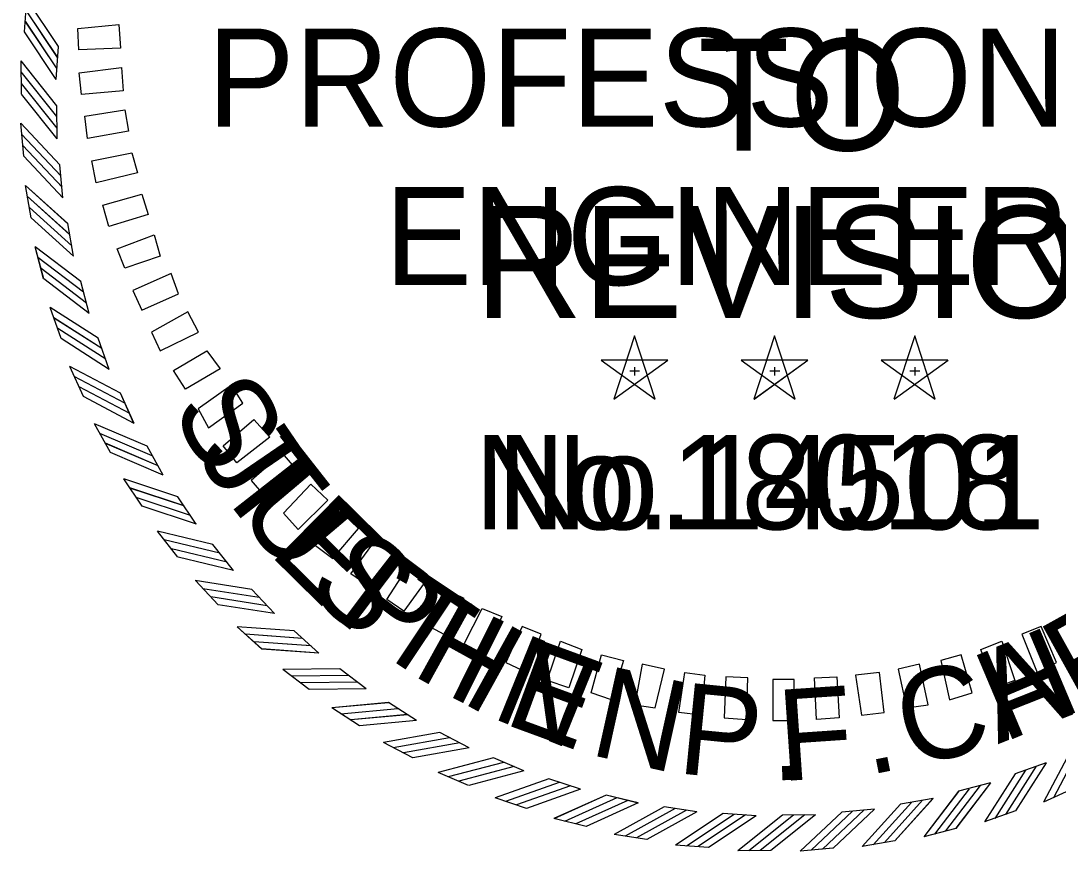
# Model space of a CAD drawing. Extents: x 16 to 1228740, y 11 to 152440.
# Drawn here: x 17.6793 to 17.7977, y 10.8149 to 10.9098 of the extents above; entities that cross this region are included whole.
import ezdxf

# ---------------------------------------------------------------- set-up
doc = ezdxf.new("R2010")
doc.units = 0
for name, color, linetype in [('STAMP_FRED', 7, 'Continuous'), ('STAMP_JUSTIN', 7, 'Continuous'), ('STAMP_PRELIM', 7, 'Continuous')]:
    doc.layers.add(name, color=color, linetype=linetype)

msp = doc.modelspace()

# ---------------------------------------------------------------- linework, layer by layer
at = {"layer": 'STAMP_FRED'}
for p, q in [((17.6797, 10.90852), (17.67998, 10.91228)), ((17.68332, 10.9031), (17.6836, 10.90687)), ((17.67937, 10.90143), (17.67934, 10.9052)), ((17.68343, 10.89632), (17.68339, 10.9001)), ((17.67963, 10.89432), (17.67928, 10.89808)), ((17.68409, 10.88957), (17.68375, 10.89333)), ((17.68047, 10.88727), (17.67982, 10.89098)), ((17.68531, 10.8829), (17.68466, 10.88662)), ((17.68189, 10.8803), (17.68093, 10.88395)), ((17.68708, 10.87635), (17.68612, 10.88)), ((17.68389, 10.87348), (17.68263, 10.87704)), ((17.68938, 10.86997), (17.68812, 10.87353)), ((17.74935, 10.87379), (17.747, 10.86655)), ((17.7517, 10.86656), (17.74936, 10.8738)), ((17.76534, 10.87379), (17.76299, 10.86655)), ((17.76769, 10.86656), (17.76535, 10.8738)), ((17.78134, 10.87379), (17.77898, 10.86655)), ((17.78369, 10.86656), (17.78134, 10.8738)), ((17.75316, 10.87103), (17.74555, 10.87103)), ((17.74555, 10.87103), (17.7517, 10.86655)), ((17.747, 10.86656), (17.75317, 10.87102)), ((17.76915, 10.87103), (17.76154, 10.87103)), ((17.76154, 10.87103), (17.7677, 10.86655)), ((17.763, 10.86656), (17.76916, 10.87102)), ((17.78514, 10.87103), (17.77753, 10.87103)), ((17.77753, 10.87103), (17.78369, 10.86655)), ((17.77899, 10.86656), (17.78515, 10.87102)), ((17.68644, 10.86685), (17.68489, 10.87029)), ((17.74881, 10.86981), (17.74994, 10.86981)), ((17.74936, 10.87022), (17.74936, 10.86926)), ((17.7648, 10.86981), (17.76593, 10.86981)), ((17.76535, 10.87022), (17.76535, 10.86926)), ((17.78079, 10.86981), (17.78193, 10.86981)), ((17.78134, 10.87022), (17.78134, 10.86926)), ((17.6922, 10.8638), (17.69065, 10.86725)), ((17.68952, 10.86045), (17.6877, 10.86375)), ((17.69552, 10.85789), (17.6937, 10.8612)), ((17.69313, 10.85433), (17.69104, 10.85746)), ((17.69932, 10.85227), (17.69723, 10.85541)), ((17.69723, 10.84852), (17.69489, 10.85148)), ((17.70357, 10.84698), (17.70122, 10.84994)), ((17.7018, 10.84308), (17.69922, 10.84583)), ((17.70824, 10.84207), (17.70566, 10.84482)), ((17.7068, 10.83802), (17.704, 10.84055)), ((17.7133, 10.83755), (17.7105, 10.84009)), ((17.71219, 10.8334), (17.7092, 10.83569)), ((17.71872, 10.83347), (17.71571, 10.83576)), ((17.72445, 10.82985), (17.72127, 10.83189)), ((17.71796, 10.82925), (17.71478, 10.83128)), ((17.73047, 10.82672), (17.72713, 10.82848)), ((17.72404, 10.82558), (17.72071, 10.82734)), ((17.73672, 10.82409), (17.73325, 10.82557)), ((17.79637, 10.82502), (17.79281, 10.82376)), ((17.73041, 10.82242), (17.72695, 10.82391)), ((17.74317, 10.82199), (17.73958, 10.82318)), ((17.78999, 10.82272), (17.78633, 10.82176)), ((17.79949, 10.82207), (17.79605, 10.82052)), ((17.73702, 10.81981), (17.73344, 10.821)), ((17.74977, 10.82042), (17.7461, 10.82132)), ((17.78344, 10.82095), (17.77972, 10.82029)), ((17.75647, 10.81941), (17.75274, 10.82)), ((17.77677, 10.81973), (17.77301, 10.81938)), ((17.74382, 10.81774), (17.74016, 10.81864)), ((17.76324, 10.81896), (17.75947, 10.81924)), ((17.77002, 10.81906), (17.76624, 10.81903)), ((17.79286, 10.81952), (17.7893, 10.81826)), ((17.78603, 10.81753), (17.78239, 10.81657)), ((17.75077, 10.81625), (17.74704, 10.81684)), ((17.77907, 10.81611), (17.77536, 10.81545)), ((17.75781, 10.81533), (17.75405, 10.81561)), ((17.76491, 10.815), (17.76114, 10.81497)), ((17.77202, 10.81526), (17.76826, 10.81492))]:
    msp.add_line(p, q, dxfattribs=at)
for points in [[(17.6836, 10.90686), (17.67997, 10.91229)], [(17.68349, 10.90561), (17.67987, 10.91104)], [(17.68343, 10.9043), (17.6798, 10.90973)], [(17.68333, 10.90309), (17.6797, 10.90852)], [(17.68339, 10.90009), (17.67933, 10.9052)], [(17.68339, 10.89884), (17.67933, 10.90394)], [(17.68343, 10.89753), (17.67937, 10.90263)], [(17.68343, 10.89631), (17.67937, 10.90142)], [(17.68375, 10.89333), (17.67928, 10.89808)], [(17.68385, 10.89208), (17.67938, 10.89683)], [(17.684, 10.89077), (17.67953, 10.89553)], [(17.6841, 10.88956), (17.67963, 10.89432)], [(17.68466, 10.88661), (17.67981, 10.89098)], [(17.68486, 10.88538), (17.68002, 10.88974)], [(17.68512, 10.88409), (17.68028, 10.88846)], [(17.68532, 10.88289), (17.68047, 10.88726)], [(17.68612, 10.88), (17.68093, 10.88395)], [(17.68643, 10.87878), (17.68124, 10.88274)], [(17.68679, 10.87752), (17.6816, 10.88148)], [(17.68709, 10.87635), (17.6819, 10.8803)], [(17.68812, 10.87353), (17.68263, 10.87704)], [(17.68853, 10.87234), (17.68303, 10.87585)], [(17.68899, 10.87112), (17.6835, 10.87463)], [(17.68939, 10.86997), (17.68389, 10.87348)], [(17.69065, 10.86724), (17.68489, 10.87029)], [(17.69116, 10.86609), (17.68539, 10.86914)], [(17.69172, 10.86491), (17.68595, 10.86796)], [(17.69221, 10.8638), (17.68644, 10.86685)], [(17.6937, 10.86119), (17.6877, 10.86375)], [(17.69429, 10.86009), (17.68829, 10.86265)], [(17.69495, 10.85895), (17.68895, 10.86151)], [(17.69553, 10.85789), (17.68953, 10.86045)], [(17.69723, 10.85541), (17.69104, 10.85746)], [(17.69791, 10.85436), (17.69172, 10.85641)], [(17.69866, 10.85328), (17.69247, 10.85534)], [(17.69933, 10.85227), (17.69314, 10.85432)], [(17.70122, 10.84994), (17.69488, 10.85148)], [(17.70199, 10.84895), (17.69566, 10.85049)], [(17.70283, 10.84794), (17.69649, 10.84948)], [(17.70358, 10.84698), (17.69724, 10.84852)], [(17.70566, 10.84482), (17.69921, 10.84583)], [(17.70651, 10.84389), (17.70006, 10.8449)], [(17.70743, 10.84296), (17.70098, 10.84397)], [(17.70825, 10.84207), (17.7018, 10.84307)], [(17.7105, 10.84008), (17.70399, 10.84055)], [(17.71142, 10.83923), (17.70492, 10.8397)], [(17.71241, 10.83837), (17.70591, 10.83885)], [(17.71331, 10.83755), (17.7068, 10.83802)], [(17.71572, 10.83576), (17.70919, 10.83569)], [(17.71671, 10.83499), (17.71019, 10.83492)], [(17.71777, 10.83422), (17.71124, 10.83415)], [(17.71872, 10.83347), (17.7122, 10.8334)], [(17.72127, 10.83188), (17.71478, 10.83128)], [(17.72232, 10.8312), (17.71583, 10.83059)], [(17.72344, 10.83051), (17.71695, 10.82991)], [(17.72446, 10.82985), (17.71796, 10.82925)], [(17.72713, 10.82848), (17.72071, 10.82734)], [(17.72823, 10.82788), (17.72181, 10.82674)], [(17.72941, 10.82729), (17.72298, 10.82615)], [(17.80024, 10.82679), (17.7972, 10.82102)], [(17.73047, 10.82672), (17.72405, 10.82558)], [(17.73325, 10.82557), (17.72694, 10.8239)], [(17.79909, 10.82629), (17.79605, 10.82052)], [(17.7344, 10.82507), (17.72809, 10.8234)], [(17.73561, 10.82458), (17.72931, 10.82291)], [(17.79522, 10.82463), (17.79171, 10.81913)], [(17.79637, 10.82502), (17.79286, 10.81953)], [(17.73673, 10.82409), (17.73042, 10.82242)], [(17.79281, 10.82376), (17.7893, 10.81826)], [(17.794, 10.82417), (17.79049, 10.81867)], [(17.73959, 10.82318), (17.73344, 10.821)], [(17.74077, 10.82277), (17.73463, 10.82059)], [(17.74203, 10.82238), (17.73588, 10.8202)], [(17.78756, 10.82206), (17.7836, 10.81687)], [(17.78882, 10.82242), (17.78486, 10.81723)], [(17.78999, 10.82272), (17.78604, 10.81753)], [(17.74317, 10.82199), (17.73703, 10.81981)], [(17.7461, 10.82131), (17.74015, 10.81863)], [(17.74732, 10.82101), (17.74137, 10.81833)], [(17.78345, 10.82095), (17.77908, 10.81611)], [(17.78634, 10.82175), (17.78239, 10.81657)], [(17.7486, 10.82072), (17.74265, 10.81804)], [(17.74977, 10.82043), (17.74383, 10.81775)], [(17.75274, 10.82), (17.74704, 10.81683)], [(17.75398, 10.81979), (17.74828, 10.81663)], [(17.77677, 10.81973), (17.77202, 10.81527)], [(17.77972, 10.82029), (17.77536, 10.81545)], [(17.78096, 10.8205), (17.77659, 10.81565)], [(17.78225, 10.82075), (17.77788, 10.81591)], [(17.75528, 10.81961), (17.74958, 10.81645)], [(17.75648, 10.81942), (17.75077, 10.81625)], [(17.75948, 10.81923), (17.75405, 10.81561)], [(17.76073, 10.81913), (17.7553, 10.81551)], [(17.76204, 10.81906), (17.75661, 10.81544)], [(17.76324, 10.81896), (17.75782, 10.81534)], [(17.76625, 10.81903), (17.76114, 10.81497)], [(17.7675, 10.81903), (17.7624, 10.81497)], [(17.76881, 10.81907), (17.76371, 10.81501)], [(17.77003, 10.81907), (17.76492, 10.81501)], [(17.77301, 10.81938), (17.76826, 10.81491)], [(17.77426, 10.81948), (17.76951, 10.81502)], [(17.77556, 10.81963), (17.77081, 10.81517)]]:
    msp.add_lwpolyline(points, dxfattribs=at)
at = {"layer": 'STAMP_JUSTIN'}
for p, q in [((17.6797, 10.90853), (17.67998, 10.91228)), ((17.68332, 10.9031), (17.6836, 10.90687)), ((17.67937, 10.90143), (17.67934, 10.9052)), ((17.68343, 10.89632), (17.6834, 10.9001)), ((17.67963, 10.89432), (17.67928, 10.89808)), ((17.6841, 10.88957), (17.68375, 10.89333)), ((17.68047, 10.88727), (17.67982, 10.89098)), ((17.68532, 10.8829), (17.68466, 10.88662)), ((17.6819, 10.88031), (17.68094, 10.88395)), ((17.68708, 10.87635), (17.68612, 10.88001)), ((17.68389, 10.87348), (17.68263, 10.87704)), ((17.68939, 10.86997), (17.68813, 10.87353)), ((17.74935, 10.87379), (17.747, 10.86655)), ((17.7517, 10.86656), (17.74936, 10.8738)), ((17.76534, 10.87379), (17.76299, 10.86655)), ((17.76769, 10.86656), (17.76535, 10.8738)), ((17.78134, 10.87379), (17.77898, 10.86655)), ((17.78369, 10.86656), (17.78134, 10.8738)), ((17.75316, 10.87103), (17.74555, 10.87103)), ((17.74555, 10.87103), (17.7517, 10.86655)), ((17.747, 10.86656), (17.75317, 10.87103)), ((17.76915, 10.87103), (17.76154, 10.87103)), ((17.76154, 10.87103), (17.7677, 10.86655)), ((17.76299, 10.86656), (17.76916, 10.87103)), ((17.78514, 10.87103), (17.77753, 10.87103)), ((17.77753, 10.87103), (17.78369, 10.86655)), ((17.77899, 10.86656), (17.78515, 10.87103)), ((17.68644, 10.86685), (17.68489, 10.87029)), ((17.74881, 10.86981), (17.74994, 10.86981)), ((17.74936, 10.87022), (17.74936, 10.86926)), ((17.7648, 10.86981), (17.76593, 10.86981)), ((17.76535, 10.87022), (17.76535, 10.86926)), ((17.78079, 10.86981), (17.78193, 10.86981)), ((17.78134, 10.87022), (17.78134, 10.86926)), ((17.69221, 10.8638), (17.69066, 10.86725)), ((17.68953, 10.86045), (17.6877, 10.86375)), ((17.69553, 10.85789), (17.6937, 10.8612)), ((17.69313, 10.85433), (17.69104, 10.85747)), ((17.69932, 10.85227), (17.69723, 10.85542)), ((17.69723, 10.84852), (17.69489, 10.85148)), ((17.70357, 10.84699), (17.70122, 10.84995)), ((17.7018, 10.84308), (17.69922, 10.84583)), ((17.70824, 10.84207), (17.70566, 10.84483)), ((17.7068, 10.83803), (17.704, 10.84055)), ((17.7133, 10.83755), (17.7105, 10.84009)), ((17.7122, 10.83341), (17.7092, 10.83569)), ((17.71872, 10.83347), (17.71572, 10.83577)), ((17.72445, 10.82985), (17.72127, 10.83189)), ((17.71796, 10.82925), (17.71478, 10.83128)), ((17.73047, 10.82672), (17.72713, 10.82849)), ((17.72404, 10.82558), (17.72071, 10.82734)), ((17.73672, 10.82409), (17.73325, 10.82558)), ((17.79637, 10.82502), (17.7928, 10.82376)), ((17.73041, 10.82243), (17.72695, 10.82391)), ((17.74317, 10.82199), (17.73958, 10.82318)), ((17.78999, 10.82272), (17.78633, 10.82176)), ((17.79949, 10.82207), (17.79605, 10.82053)), ((17.73702, 10.81981), (17.73344, 10.821)), ((17.74977, 10.82043), (17.7461, 10.82132)), ((17.78344, 10.82095), (17.77972, 10.8203)), ((17.75647, 10.81942), (17.75274, 10.82)), ((17.77677, 10.81973), (17.77301, 10.81939)), ((17.74382, 10.81775), (17.74016, 10.81864)), ((17.76324, 10.81896), (17.75947, 10.81924)), ((17.77002, 10.81907), (17.76624, 10.81903)), ((17.79285, 10.81952), (17.7893, 10.81827)), ((17.78603, 10.81753), (17.78239, 10.81657)), ((17.75077, 10.81625), (17.74704, 10.81684)), ((17.77907, 10.81611), (17.77536, 10.81545)), ((17.75781, 10.81534), (17.75405, 10.81561)), ((17.76491, 10.81501), (17.76114, 10.81497)), ((17.77201, 10.81527), (17.76826, 10.81492))]:
    msp.add_line(p, q, dxfattribs=at)
for points in [[(17.6836, 10.90686), (17.67998, 10.91229)], [(17.6835, 10.90561), (17.67987, 10.91104)], [(17.68343, 10.9043), (17.67981, 10.90973)], [(17.68333, 10.9031), (17.6797, 10.90852)], [(17.68339, 10.90009), (17.67933, 10.9052)], [(17.68339, 10.89884), (17.67933, 10.90394)], [(17.68343, 10.89753), (17.67938, 10.90263)], [(17.68343, 10.89631), (17.67938, 10.90142)], [(17.68375, 10.89333), (17.67928, 10.89808)], [(17.68385, 10.89208), (17.67938, 10.89683)], [(17.684, 10.89077), (17.67953, 10.89553)], [(17.6841, 10.88957), (17.67963, 10.89432)], [(17.68466, 10.88662), (17.67981, 10.89098)], [(17.68487, 10.88538), (17.68002, 10.88975)], [(17.68512, 10.88409), (17.68028, 10.88846)], [(17.68532, 10.8829), (17.68048, 10.88726)], [(17.68612, 10.88), (17.68093, 10.88395)], [(17.68643, 10.87878), (17.68124, 10.88274)], [(17.68679, 10.87752), (17.6816, 10.88148)], [(17.68709, 10.87635), (17.6819, 10.8803)], [(17.68812, 10.87353), (17.68263, 10.87704)], [(17.68853, 10.87234), (17.68304, 10.87585)], [(17.689, 10.87112), (17.6835, 10.87463)], [(17.68939, 10.86997), (17.68389, 10.87348)], [(17.69066, 10.86725), (17.68489, 10.87029)], [(17.69116, 10.8661), (17.68539, 10.86914)], [(17.69172, 10.86491), (17.68596, 10.86796)], [(17.69221, 10.8638), (17.68644, 10.86685)], [(17.6937, 10.86119), (17.6877, 10.86375)], [(17.69429, 10.86009), (17.68829, 10.86265)], [(17.69495, 10.85896), (17.68895, 10.86152)], [(17.69553, 10.85789), (17.68953, 10.86045)], [(17.69723, 10.85541), (17.69104, 10.85747)], [(17.69792, 10.85436), (17.69172, 10.85642)], [(17.69867, 10.85329), (17.69247, 10.85534)], [(17.69933, 10.85227), (17.69314, 10.85433)], [(17.70122, 10.84994), (17.69489, 10.85148)], [(17.702, 10.84895), (17.69566, 10.85049)], [(17.70283, 10.84794), (17.69649, 10.84948)], [(17.70358, 10.84698), (17.69724, 10.84852)], [(17.70566, 10.84482), (17.69921, 10.84583)], [(17.70651, 10.8439), (17.70006, 10.8449)], [(17.70743, 10.84296), (17.70098, 10.84397)], [(17.70825, 10.84207), (17.7018, 10.84308)], [(17.7105, 10.84008), (17.704, 10.84056)], [(17.71143, 10.83923), (17.70492, 10.8397)], [(17.71242, 10.83838), (17.70591, 10.83885)], [(17.71331, 10.83755), (17.7068, 10.83803)], [(17.71572, 10.83576), (17.7092, 10.83569)], [(17.71671, 10.83499), (17.71019, 10.83492)], [(17.71777, 10.83422), (17.71124, 10.83415)], [(17.71872, 10.83347), (17.7122, 10.83341)], [(17.72127, 10.83189), (17.71478, 10.83128)], [(17.72233, 10.8312), (17.71583, 10.83059)], [(17.72344, 10.83052), (17.71695, 10.82991)], [(17.72446, 10.82985), (17.71796, 10.82925)], [(17.72713, 10.82848), (17.72071, 10.82734)], [(17.72824, 10.82788), (17.72181, 10.82674)], [(17.72941, 10.8273), (17.72298, 10.82616)], [(17.80024, 10.8268), (17.7972, 10.82103)], [(17.73047, 10.82672), (17.72405, 10.82558)], [(17.73325, 10.82557), (17.72694, 10.82391)], [(17.79909, 10.82629), (17.79605, 10.82052)], [(17.7344, 10.82507), (17.72809, 10.8234)], [(17.73561, 10.82458), (17.72931, 10.82291)], [(17.79522, 10.82463), (17.79171, 10.81913)], [(17.79637, 10.82503), (17.79286, 10.81953)], [(17.73673, 10.82409), (17.73042, 10.82243)], [(17.79281, 10.82376), (17.7893, 10.81826)], [(17.794, 10.82417), (17.79049, 10.81867)], [(17.73959, 10.82318), (17.73344, 10.821)], [(17.74077, 10.82277), (17.73463, 10.82059)], [(17.74203, 10.82239), (17.73588, 10.8202)], [(17.78756, 10.82206), (17.7836, 10.81688)], [(17.78882, 10.82243), (17.78486, 10.81724)], [(17.78999, 10.82272), (17.78604, 10.81754)], [(17.74317, 10.82199), (17.73703, 10.81981)], [(17.7461, 10.82132), (17.74015, 10.81864)], [(17.74732, 10.82101), (17.74137, 10.81833)], [(17.78344, 10.82096), (17.77908, 10.81611)], [(17.78634, 10.82176), (17.78238, 10.81657)], [(17.7486, 10.82073), (17.74265, 10.81805)], [(17.74977, 10.82043), (17.74383, 10.81775)], [(17.75274, 10.82), (17.74704, 10.81684)], [(17.75398, 10.81979), (17.74828, 10.81663)], [(17.77677, 10.81974), (17.77202, 10.81527)], [(17.77972, 10.82029), (17.77536, 10.81545)], [(17.78096, 10.8205), (17.77659, 10.81566)], [(17.78225, 10.82076), (17.77788, 10.81591)], [(17.75528, 10.81962), (17.74958, 10.81645)], [(17.75648, 10.81942), (17.75077, 10.81626)], [(17.75948, 10.81924), (17.75405, 10.81561)], [(17.76073, 10.81913), (17.7553, 10.81551)], [(17.76204, 10.81906), (17.75661, 10.81544)], [(17.76324, 10.81896), (17.75782, 10.81534)], [(17.76625, 10.81903), (17.76114, 10.81497)], [(17.7675, 10.81903), (17.7624, 10.81497)], [(17.76881, 10.81907), (17.76371, 10.81501)], [(17.77003, 10.81907), (17.76492, 10.81501)], [(17.77301, 10.81938), (17.76826, 10.81492)], [(17.77426, 10.81949), (17.76951, 10.81502)], [(17.77556, 10.81964), (17.77081, 10.81517)]]:
    msp.add_lwpolyline(points, dxfattribs=at)
at = {"layer": 'STAMP_PRELIM'}
for p, q in [((17.68578, 10.90891), (17.69046, 10.90935)), ((17.6859, 10.90647), (17.68578, 10.90891)), ((17.69046, 10.90935), (17.69065, 10.90666)), ((17.69065, 10.90666), (17.6859, 10.90647)), ((17.68596, 10.90385), (17.69078, 10.90447)), ((17.68621, 10.90135), (17.68596, 10.90385)), ((17.69078, 10.90447), (17.69096, 10.90178)), ((17.69096, 10.90178), (17.68621, 10.90135)), ((17.68659, 10.89891), (17.69115, 10.8996)), ((17.69115, 10.8996), (17.69159, 10.89716)), ((17.6869, 10.89635), (17.68659, 10.89891)), ((17.69159, 10.89716), (17.6869, 10.89635)), ((17.6874, 10.89378), (17.69196, 10.89472)), ((17.69196, 10.89472), (17.69259, 10.89241)), ((17.6879, 10.89128), (17.6874, 10.89378)), ((17.69259, 10.89241), (17.6879, 10.89128)), ((17.68865, 10.88872), (17.69309, 10.88997)), ((17.69309, 10.88997), (17.69384, 10.88766)), ((17.68934, 10.88628), (17.68865, 10.88872)), ((17.69384, 10.88766), (17.68934, 10.88628)), ((17.69028, 10.88372), (17.69453, 10.88535)), ((17.69453, 10.88535), (17.69521, 10.88291)), ((17.69115, 10.88153), (17.69028, 10.88372)), ((17.69521, 10.88291), (17.69115, 10.88153)), ((17.69646, 10.88091), (17.69209, 10.87897)), ((17.69728, 10.8786), (17.69646, 10.88091)), ((17.69209, 10.87897), (17.69309, 10.87672)), ((17.69309, 10.87672), (17.69728, 10.8786)), ((17.69834, 10.87653), (17.69421, 10.87422)), ((17.69959, 10.87422), (17.69834, 10.87653)), ((17.69421, 10.87422), (17.69521, 10.8721)), ((17.69521, 10.8721), (17.69959, 10.87422)), ((17.69671, 10.86985), (17.70053, 10.8721)), ((17.70053, 10.8721), (17.70203, 10.87003)), ((17.69809, 10.86772), (17.69671, 10.86985)), ((17.70203, 10.87003), (17.69809, 10.86772)), ((17.70334, 10.86816), (17.69953, 10.86547)), ((17.70465, 10.8661), (17.70334, 10.86816)), ((17.70071, 10.86328), (17.70465, 10.8661)), ((17.69953, 10.86547), (17.70071, 10.86328)), ((17.7024, 10.86122), (17.7059, 10.86422)), ((17.7059, 10.86422), (17.70771, 10.86222)), ((17.70396, 10.85928), (17.7024, 10.86122)), ((17.70771, 10.86222), (17.70396, 10.85928)), ((17.70915, 10.86041), (17.70559, 10.85728)), ((17.71078, 10.85853), (17.70915, 10.86041)), ((17.70721, 10.85535), (17.71078, 10.85853)), ((17.70559, 10.85728), (17.70721, 10.85535)), ((17.70928, 10.85353), (17.7124, 10.85685)), ((17.7124, 10.85685), (17.71434, 10.85503)), ((17.71434, 10.85503), (17.71096, 10.85166)), ((17.71096, 10.85166), (17.70928, 10.85353)), ((17.71603, 10.85353), (17.71278, 10.84997)), ((17.71784, 10.85178), (17.71603, 10.85353)), ((17.7149, 10.84835), (17.71784, 10.85178)), ((17.71696, 10.8466), (17.71978, 10.85047)), ((17.71978, 10.85047), (17.72171, 10.84891)), ((17.71278, 10.84997), (17.7149, 10.84835)), ((17.72171, 10.84891), (17.7189, 10.84528)), ((17.72109, 10.84366), (17.72365, 10.84766)), ((17.72365, 10.84766), (17.72584, 10.84622)), ((17.7189, 10.84528), (17.71696, 10.8466)), ((17.72584, 10.84622), (17.72303, 10.84235)), ((17.72771, 10.84485), (17.72559, 10.84078)), ((17.7299, 10.84378), (17.72771, 10.84485)), ((17.72303, 10.84235), (17.72109, 10.84366)), ((17.72759, 10.83972), (17.7299, 10.84378)), ((17.7299, 10.8386), (17.73196, 10.84266)), ((17.73196, 10.84266), (17.73421, 10.84172)), ((17.73421, 10.84172), (17.73228, 10.83735)), ((17.72559, 10.84078), (17.72759, 10.83972)), ((17.73653, 10.8406), (17.73465, 10.83647)), ((17.73871, 10.83972), (17.73653, 10.8406)), ((17.79578, 10.8406), (17.79358, 10.83972)), ((17.79753, 10.83647), (17.79578, 10.8406)), ((17.73228, 10.83735), (17.7299, 10.8386)), ((17.73709, 10.83535), (17.73871, 10.83972)), ((17.7394, 10.83441), (17.7409, 10.83891)), ((17.7409, 10.83891), (17.74334, 10.83797)), ((17.7889, 10.83797), (17.79128, 10.83891)), ((17.79128, 10.83891), (17.79278, 10.83441)), ((17.79358, 10.83972), (17.79533, 10.83535)), ((17.74334, 10.83797), (17.74184, 10.8336)), ((17.79046, 10.8336), (17.7889, 10.83797)), ((17.73465, 10.83647), (17.73709, 10.83535)), ((17.7444, 10.83303), (17.74559, 10.83735)), ((17.74559, 10.83735), (17.74809, 10.83672)), ((17.74809, 10.83672), (17.74671, 10.83222)), ((17.75021, 10.83628), (17.7494, 10.83166)), ((17.75278, 10.83572), (17.75021, 10.83628)), ((17.7819, 10.83628), (17.77946, 10.83572)), ((17.7829, 10.83166), (17.7819, 10.83628)), ((17.78665, 10.83735), (17.78433, 10.83672)), ((17.78433, 10.83672), (17.78533, 10.83222)), ((17.7879, 10.83303), (17.78665, 10.83735)), ((17.79533, 10.83535), (17.79753, 10.83647)), ((17.75171, 10.83128), (17.75278, 10.83572)), ((17.7544, 10.83078), (17.75509, 10.83535)), ((17.75509, 10.83535), (17.7574, 10.83503)), ((17.77734, 10.83535), (17.77459, 10.83503)), ((17.77784, 10.83078), (17.77734, 10.83535)), ((17.77946, 10.83572), (17.7804, 10.83128)), ((17.74184, 10.8336), (17.7394, 10.83441)), ((17.7574, 10.83503), (17.75696, 10.83047)), ((17.75978, 10.83485), (17.75959, 10.83016)), ((17.76228, 10.83472), (17.75978, 10.83485)), ((17.76215, 10.82997), (17.76228, 10.83472)), ((17.76515, 10.83453), (17.76515, 10.82985)), ((17.76759, 10.83453), (17.76515, 10.83453)), ((17.76759, 10.82985), (17.76759, 10.83453)), ((17.7699, 10.83472), (17.77246, 10.83485)), ((17.77015, 10.82997), (17.7699, 10.83472)), ((17.77246, 10.83485), (17.77271, 10.83016)), ((17.77459, 10.83503), (17.77528, 10.83047)), ((17.79278, 10.83441), (17.79046, 10.8336)), ((17.74671, 10.83222), (17.7444, 10.83303)), ((17.78533, 10.83222), (17.7879, 10.83303)), ((17.7494, 10.83166), (17.75171, 10.83128)), ((17.7804, 10.83128), (17.7829, 10.83166)), ((17.75696, 10.83047), (17.7544, 10.83078)), ((17.77528, 10.83047), (17.77784, 10.83078)), ((17.75959, 10.83016), (17.76215, 10.82997)), ((17.76515, 10.82985), (17.76759, 10.82985)), ((17.77271, 10.83016), (17.77015, 10.82997))]:
    msp.add_line(p, q, dxfattribs=at)

# ---------------------------------------------------------------- texts
at = {"layer": 'STAMP_FRED'}
for s, height, p in [('PROFESSIONAL', 0.0111938, (17.70056, 10.89771)), ('ENGINEER', 0.011194, (17.72082, 10.87959)), ('No.14501', 0.010794, (17.73362, 10.85168))]:
    msp.add_text(s, height=height, dxfattribs=at).set_placement(p)
for s, rotation, p in [('S', 300.7985, (17.69626, 10.86535)), ('T', 308.0945, (17.70135, 10.85681)), ('E', 315.3905, (17.70747, 10.849)), ('P', 323.0513, (17.71492, 10.8417)), ('H', 331.0769, (17.7237, 10.83519)), ('H', 22.8786, (17.79144, 10.82727)), ('E', 339.8321, (17.7342, 10.82956)), ('N', 347.4929, (17.744, 10.82599)), ('F', 3.9089, (17.76608, 10.82291)), ('.', 11.205, (17.77599, 10.82359))]:
    msp.add_text(s, height=0.01042, rotation=rotation, dxfattribs=at).set_placement(p)
at = {"layer": 'STAMP_JUSTIN'}
for s, height, p in [('PROFESSIONAL', 0.0111936, (17.70056, 10.89771)), ('ENGINEER', 0.011194, (17.72082, 10.87959)), ('No.18018', 0.010794, (17.73105, 10.85168))]:
    msp.add_text(s, height=height, dxfattribs=at).set_placement(p)
for s, rotation, p in [('J', 304.3679, (17.69917, 10.86027)), ('U', 310.2047, (17.70366, 10.85372)), ('S', 318.9599, (17.71157, 10.84482)), ('T', 326.256, (17.71914, 10.8384)), ('R', 29.0016, (17.80002, 10.83092)), ('I', 333.552, (17.72747, 10.83299)), ('N', 337.9296, (17.73277, 10.83027)), ('A', 21.7056, (17.79084, 10.82713)), ('C', 14.0448, (17.78077, 10.82444)), ('P', 354.3456, (17.75409, 10.82384)), ('.', 2.3712, (17.76498, 10.82297))]:
    msp.add_text(s, height=0.01042, rotation=rotation, dxfattribs=at).set_placement(p)
at = {"layer": 'STAMP_PRELIM'}
for s, p in [('TO', (17.75659, 10.89497)), ('REVISION', (17.73109, 10.87585))]:
    msp.add_text(s, height=0.012794, dxfattribs=at).set_placement(p)

doc.saveas('drawing.dxf')
